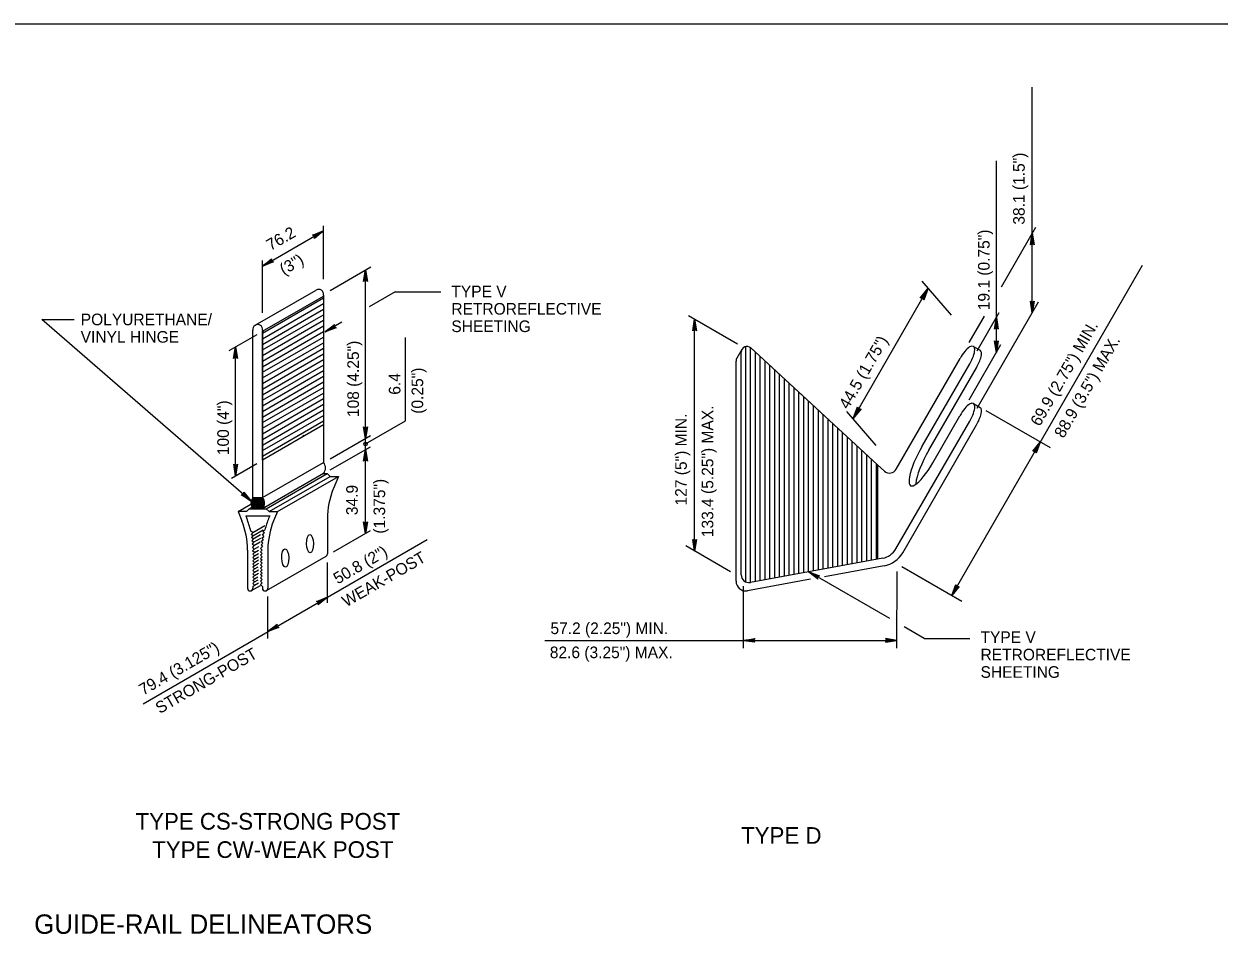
# Model space of a CAD drawing. Extents: x 640253 to 641999, y 298458 to 299646.
# Drawn here: x 640490.1 to 640798.8, y 298801.7 to 299036.6 of the extents above; entities that cross this region are included whole.
import ezdxf

# ---------------------------------------------------------------- set-up
doc = ezdxf.new("R2010")
doc.units = 0
doc.layers.add('1', color=7, linetype='Continuous')
doc.layers.add('2', color=7, linetype='Continuous')

msp = doc.modelspace()

# ---------------------------------------------------------------- linework, layer by layer
at = {"layer": '1'}
msp.add_line((640293.31, 299036.63), (641079.31, 299036.63), dxfattribs=at)
at = {"layer": '2'}
for p, q in [((640750.54, 298962.09), (640750.55, 299020.27)), ((640741.28, 298960.84), (640741.29, 299001.32)), ((640551.76, 298974.1), (640567.51, 298983.19)), ((640567.51, 298970.72), (640567.51, 298984.49)), ((640742.56, 298968.76), (640751.44, 298984.14)), ((640551.76, 298962.03), (640551.76, 298975.56)), ((640569.19, 298967.84), (640579.72, 298973.91)), ((640729.75, 298889.07), (640778.99, 298974.33)), ((640578.36, 298929.66), (640578.36, 298973.13)), ((640549.88, 298958.85), (640565.62, 298967.94)), ((640586.04, 298967.48), (640579.26, 298963.62)), ((640586.04, 298967.48), (640597.84, 298967.48)), ((640704.26, 298934.75), (640723.7, 298968.41)), ((640729.66, 298961.46), (640722.11, 298970.27)), ((640551.76, 298956.81), (640567.51, 298965.9)), ((640551.76, 298955.36), (640567.51, 298964.45)), ((640567.51, 298966.65), (640567.51, 298923.44)), ((640736.28, 298937.41), (640752.15, 298964.88)), ((640551.76, 298953.92), (640567.51, 298963.01)), ((640551.76, 298952.48), (640567.51, 298961.56)), ((640674.43, 298954.01), (640661.77, 298961.32)), ((640734.29, 298954.44), (640738.18, 298961.17)), ((640736.31, 298952.24), (640742.03, 298962.14)), ((640494.74, 298960.33), (640503.1, 298960.33)), ((640548.82, 298913.46), (640494.74, 298960.33)), ((640551.76, 298951.03), (640567.51, 298960.12)), ((640551.76, 298949.59), (640567.51, 298958.68)), ((640572.24, 298959.61), (640567.94, 298957.16)), ((640663.36, 298900.57), (640663.36, 298960.4)), ((640741.28, 298951.81), (640741.28, 298960.84)), ((640543.17, 298952.33), (640550.37, 298956.48)), ((640549.27, 298914.35), (640549.27, 298957.56)), ((640551.76, 298957.56), (640551.76, 298914.35)), ((640551.76, 298957.02), (640551.99, 298957.42)), ((640551.76, 298957.06), (640551.96, 298957.4)), ((640551.76, 298948.15), (640567.51, 298957.24)), ((640551.76, 298946.7), (640567.51, 298955.79)), ((640588.68, 298934.17), (640588.68, 298955.67)), ((640544.78, 298919.99), (640544.78, 298953.26)), ((640551.76, 298945.26), (640567.51, 298954.35)), ((640551.76, 298943.82), (640567.51, 298952.9)), ((640674.3, 298950.42), (640675.62, 298952.7)), ((640675.38, 298894.43), (640675.38, 298951.88)), ((640676.55, 298892.62), (640676.56, 298953.34)), ((640677.8, 298892.48), (640677.8, 298953.05)), ((640695.7, 298936.55), (640677.87, 298953)), ((640677.9, 298952.98), (640710.55, 298922.83)), ((640679.05, 298892.71), (640679.05, 298951.91)), ((640734.24, 298939.62), (640742.46, 298953.85)), ((640735.34, 298953.4), (640737.1, 298952.38)), ((640551.76, 298942.37), (640567.51, 298951.46)), ((640551.76, 298940.93), (640567.51, 298950.02)), ((640674.06, 298892.76), (640674.06, 298949.61)), ((640680.3, 298892.93), (640680.31, 298950.76)), ((640681.55, 298893.16), (640681.56, 298949.61)), ((640715.38, 298921.69), (640731.89, 298950.28)), ((640722.09, 298927.61), (640734.39, 298948.9)), ((640551.76, 298939.49), (640567.51, 298948.57)), ((640551.76, 298938.04), (640567.51, 298947.13)), ((640551.76, 298936.6), (640567.51, 298945.69)), ((640682.8, 298893.39), (640682.8, 298948.45)), ((640684.05, 298893.62), (640684.05, 298947.3)), ((640685.3, 298893.85), (640685.3, 298946.14)), ((640723.82, 298926.61), (640736.12, 298947.9)), ((640551.76, 298935.16), (640567.51, 298944.24)), ((640551.76, 298933.71), (640567.51, 298942.8)), ((640686.55, 298894.08), (640686.55, 298944.99)), ((640687.8, 298894.31), (640687.8, 298943.83)), ((640689.05, 298894.54), (640689.05, 298942.68)), ((640551.76, 298932.27), (640567.51, 298941.36)), ((640551.76, 298930.82), (640567.51, 298939.91)), ((640690.3, 298894.77), (640690.3, 298941.53)), ((640691.55, 298895), (640691.55, 298940.37)), ((640551.76, 298929.38), (640567.51, 298938.47)), ((640551.76, 298927.94), (640567.51, 298937.03)), ((640692.8, 298895.23), (640692.8, 298939.22)), ((640694.05, 298895.46), (640694.06, 298938.06)), ((640695.3, 298895.69), (640695.3, 298936.91)), ((640710.22, 298927.8), (640702.67, 298936.61)), ((640735.35, 298938.66), (640737.12, 298937.64)), ((640755.23, 298927.18), (640738.62, 298936.77)), ((640551.76, 298926.5), (640567.51, 298935.58)), ((640551.76, 298925.05), (640567.51, 298934.14)), ((640578.36, 298928.21), (640588.68, 298934.17)), ((640696.55, 298895.92), (640696.55, 298935.76)), ((640697.8, 298896.14), (640697.8, 298934.6)), ((640699.05, 298896.37), (640699.05, 298933.45)), ((640715.35, 298901.15), (640734.39, 298934.12)), ((640724.85, 298923.36), (640731.87, 298935.51)), ((640562.12, 298930), (640562.43, 298930.53)), ((640569.22, 298924.38), (640579.61, 298930.38)), ((640700.3, 298896.6), (640700.3, 298932.29)), ((640701.55, 298896.83), (640701.55, 298931.14)), ((640717.08, 298900.15), (640736.12, 298933.12)), ((640569.22, 298921.5), (640579.61, 298927.49)), ((640578.36, 298926.77), (640578.36, 298929.66)), ((640702.8, 298897.06), (640702.8, 298929.98)), ((640704.05, 298897.29), (640704.05, 298928.83)), ((640705.3, 298897.52), (640705.3, 298927.68)), ((640578.36, 298905.13), (640578.36, 298926.77)), ((640706.55, 298897.75), (640706.55, 298926.52)), ((640707.8, 298897.98), (640707.8, 298925.37)), ((640709.05, 298898.21), (640709.05, 298924.21)), ((640543.72, 298919.38), (640550.3, 298923.18)), ((640551.76, 298914.35), (640567.51, 298923.44)), ((640710.3, 298898.44), (640710.3, 298923.06)), ((640712.37, 298921.15), (640710.55, 298922.83)), ((640710.55, 298922.83), (640710.55, 298898.48)), ((640567.51, 298920.55), (640551.76, 298911.46)), ((640552.74, 298911.46), (640568.49, 298920.55)), ((640553.45, 298910.75), (640569.2, 298919.85)), ((640555.6, 298910.75), (640571.35, 298919.85)), ((640567.51, 298920.55), (640568.49, 298920.55)), ((640568.49, 298920.55), (640569.2, 298919.85)), ((640569.2, 298919.85), (640571.35, 298919.85)), ((640571.35, 298919.85), (640570.01, 298916.58)), ((640545.43, 298910.75), (640548.77, 298912.67)), ((640548.29, 298911.46), (640549, 298911.87)), ((640548.77, 298913.01), (640550.11, 298914.35)), ((640548.79, 298912.68), (640550.46, 298914.35)), ((640548.84, 298912.38), (640550.81, 298914.35)), ((640548.85, 298913.45), (640549.75, 298914.35)), ((640548.92, 298912.1), (640551.17, 298914.35)), ((640549.01, 298911.84), (640551.52, 298914.35)), ((640549.07, 298914.03), (640549.4, 298914.35)), ((640549.15, 298911.63), (640551.81, 298914.29)), ((640549.27, 298914.35), (640551.76, 298914.35)), ((640549.34, 298911.46), (640551.95, 298914.07)), ((640549.69, 298911.46), (640552.08, 298913.85)), ((640550.04, 298911.46), (640552.16, 298913.57)), ((640550.4, 298911.46), (640552.23, 298913.3)), ((640550.75, 298911.46), (640552.27, 298912.98)), ((640551.1, 298911.46), (640552.24, 298912.6)), ((640551.46, 298911.46), (640552.13, 298912.14)), ((640547.58, 298910.75), (640545.43, 298910.75)), ((640545.43, 298910.75), (640546.4, 298908.39)), ((640547.42, 298909.64), (640553.61, 298909.64)), ((640547.42, 298909.64), (640547.68, 298908.99)), ((640548.29, 298911.46), (640547.58, 298910.75)), ((640548.29, 298911.46), (640552.74, 298911.46)), ((640551.76, 298911.46), (640551.77, 298911.46)), ((640552.74, 298911.46), (640553.45, 298910.75)), ((640553.61, 298909.64), (640553.34, 298908.99)), ((640553.45, 298910.75), (640555.6, 298910.75)), ((640555.6, 298910.75), (640554.63, 298908.39)), ((640568.51, 298908.92), (640568.51, 298899.86)), ((640549.2, 298905.41), (640548.72, 298905.74)), ((640549.22, 298905.39), (640552.36, 298907.2)), ((640549.25, 298904.5), (640551.95, 298906.06)), ((640551.86, 298905.67), (640552.38, 298906.04)), ((640551.86, 298905.67), (640552.21, 298905.19)), ((640570.1, 298900.36), (640579.61, 298905.86)), ((640520.9, 298861.15), (640594.28, 298903.52)), ((640549.22, 298905.39), (640548.81, 298904.8)), ((640549.25, 298904.5), (640548.81, 298904.8)), ((640549.25, 298904.5), (640548.93, 298904.06)), ((640549.35, 298903.69), (640548.93, 298904.06)), ((640549.35, 298903.69), (640548.96, 298903.24)), ((640549.45, 298902.82), (640548.96, 298903.24)), ((640549.45, 298902.82), (640549.06, 298902.37)), ((640549.35, 298903.69), (640551.26, 298904.8)), ((640549.45, 298902.82), (640551.29, 298903.89)), ((640549.52, 298901.97), (640551.16, 298902.92)), ((640551.37, 298902.18), (640551.83, 298902.58)), ((640551.44, 298903.03), (640551.93, 298903.45)), ((640551.44, 298903.03), (640551.83, 298902.58)), ((640551.54, 298903.9), (640552.06, 298904.35)), ((640551.54, 298903.9), (640551.93, 298903.45)), ((640551.71, 298904.83), (640552.21, 298905.19)), ((640551.71, 298904.83), (640552.06, 298904.35)), ((640547.88, 298900.83), (640547.88, 298890.99)), ((640549.52, 298901.97), (640549.06, 298902.37)), ((640549.52, 298901.97), (640549.13, 298901.52)), ((640549.61, 298901.04), (640549.13, 298901.52)), ((640549.61, 298901.04), (640549.19, 298900.62)), ((640549.65, 298900.17), (640549.19, 298900.62)), ((640549.65, 298900.17), (640549.23, 298899.75)), ((640549.66, 298899.31), (640549.23, 298899.75)), ((640549.66, 298899.31), (640549.24, 298898.89)), ((640549.61, 298901.04), (640550.83, 298901.75)), ((640549.65, 298900.17), (640550.76, 298900.81)), ((640549.66, 298899.31), (640550.73, 298899.94)), ((640551.23, 298899.52), (640551.66, 298899.95)), ((640551.23, 298899.52), (640551.65, 298899.1)), ((640551.24, 298900.37), (640551.7, 298900.83)), ((640551.24, 298900.37), (640551.66, 298899.95)), ((640551.28, 298901.25), (640551.76, 298901.73)), ((640551.28, 298901.25), (640551.7, 298900.83)), ((640551.37, 298902.18), (640551.76, 298901.73)), ((640553.15, 298900.83), (640553.15, 298890.99)), ((640672.59, 298895.24), (640661.07, 298901.9)), ((640549.66, 298898.47), (640549.24, 298898.89)), ((640549.66, 298898.47), (640549.24, 298898.05)), ((640549.66, 298897.63), (640549.24, 298898.05)), ((640549.66, 298897.63), (640549.24, 298897.21)), ((640549.66, 298896.79), (640549.24, 298897.21)), ((640549.66, 298896.79), (640549.24, 298896.37)), ((640549.66, 298895.95), (640549.24, 298896.37)), ((640549.66, 298898.47), (640550.75, 298899.11)), ((640549.66, 298897.63), (640550.73, 298898.26)), ((640549.66, 298896.79), (640550.73, 298897.41)), ((640549.66, 298895.95), (640550.62, 298896.51)), ((640551.23, 298898.68), (640551.65, 298899.1)), ((640551.23, 298898.68), (640551.65, 298898.26)), ((640551.23, 298897.84), (640551.65, 298898.26)), ((640551.23, 298897.84), (640551.65, 298897.42)), ((640551.23, 298897), (640551.65, 298897.42)), ((640551.23, 298897), (640551.65, 298896.58)), ((640551.23, 298896.16), (640551.65, 298896.58)), ((640552.8, 298890.37), (640568.16, 298899.25)), ((640568.51, 298887.18), (640568.51, 298897.6)), ((640710.55, 298898.48), (640677.74, 298892.47)), ((640712.28, 298896.77), (640696.92, 298893.95)), ((640711.92, 298898.73), (640710.55, 298898.48)), ((640732.35, 298887.57), (640716.86, 298896.51)), ((640549.66, 298895.95), (640549.24, 298895.53)), ((640549.66, 298895.11), (640549.24, 298895.53)), ((640549.66, 298895.11), (640549.24, 298894.69)), ((640549.66, 298894.27), (640549.24, 298894.69)), ((640549.66, 298894.27), (640549.24, 298893.85)), ((640549.66, 298893.43), (640549.24, 298893.85)), ((640549.66, 298893.43), (640549.24, 298893.01)), ((640549.66, 298895.11), (640550.7, 298895.72)), ((640549.66, 298894.27), (640550.71, 298894.88)), ((640549.66, 298893.43), (640550.52, 298893.93)), ((640549.66, 298892.59), (640550.62, 298893.15)), ((640551.23, 298896.16), (640551.65, 298895.74)), ((640551.23, 298895.32), (640551.65, 298895.74)), ((640551.23, 298895.32), (640551.65, 298894.9)), ((640551.23, 298894.48), (640551.65, 298894.9)), ((640551.23, 298894.48), (640551.65, 298894.06)), ((640551.23, 298893.64), (640551.65, 298894.06)), ((640551.23, 298893.64), (640551.65, 298893.22)), ((640551.23, 298892.8), (640551.65, 298893.22)), ((640693.24, 298893.28), (640677.02, 298890.3)), ((640713.78, 298883.12), (640692.81, 298895.23)), ((640715.61, 298875.5), (640715.62, 298895.26)), ((640548.95, 298890.37), (640551.25, 298891.7)), ((640549.66, 298892.59), (640549.24, 298893.01)), ((640549.66, 298892.59), (640549.24, 298892.17)), ((640549.66, 298891.75), (640549.24, 298892.17)), ((640549.3, 298891.4), (640549.66, 298891.75)), ((640549.3, 298891.4), (640549.3, 298890.99)), ((640549.66, 298891.75), (640550.71, 298892.36)), ((640551.23, 298892.8), (640551.65, 298892.38)), ((640551.23, 298891.96), (640551.65, 298892.38)), ((640551.23, 298891.96), (640551.73, 298891.46)), ((640551.73, 298891.46), (640551.73, 298890.99)), ((640675.94, 298875.5), (640675.94, 298891.49)), ((640553.15, 298878.02), (640553.15, 298888.85)), ((640722.62, 298878.01), (640717.48, 298880.98)), ((640722.62, 298878.01), (640734.42, 298878.01)), ((640624.71, 298877.52), (640715.61, 298877.52))]:
    msp.add_line(p, q, dxfattribs=at)
for points in [[(640564.86, 298982.07), (640565.05, 298981.95), (640567.51, 298983.19), (640564.86, 298982.07), (640564.67, 298982.11), (640567.51, 298983.19), (640565.2, 298981.7), (640565.21, 298981.47), (640567.51, 298983.19), (640565.15, 298981.28), (640565.21, 298981.47)], [(640750.18, 298979.73), (640750.39, 298979.84), (640750.54, 298982.58), (640750.18, 298979.73), (640750.06, 298979.58), (640750.54, 298982.58), (640750.68, 298979.84), (640750.88, 298979.74), (640750.54, 298982.58), (640751.02, 298979.58), (640750.88, 298979.74)], [(640554.41, 298975.22), (640554.22, 298975.34), (640551.76, 298974.1), (640554.41, 298975.22), (640554.6, 298975.18), (640551.76, 298974.1), (640554.07, 298975.59), (640554.06, 298975.82), (640551.76, 298974.1), (640554.12, 298976.01), (640554.06, 298975.82)], [(640578, 298970.28), (640578.21, 298970.38), (640578.36, 298973.13), (640578, 298970.28), (640577.87, 298970.13), (640578.36, 298973.13), (640578.49, 298970.39), (640578.7, 298970.29), (640578.36, 298973.13), (640578.83, 298970.13), (640578.7, 298970.29)], [(640721.82, 298965.93), (640722.07, 298965.92), (640723.7, 298968.41), (640721.82, 298965.93), (640721.63, 298965.86), (640723.7, 298968.41), (640722.34, 298965.77), (640722.48, 298965.56), (640723.7, 298968.41), (640722.53, 298965.34), (640722.48, 298965.56)], [(640750.9, 298964.94), (640750.69, 298964.84), (640750.54, 298962.09), (640750.9, 298964.94), (640751.02, 298965.09), (640750.54, 298962.09), (640750.4, 298964.84), (640750.2, 298964.94), (640750.54, 298962.09), (640750.06, 298965.09), (640750.2, 298964.94)], [(640570.6, 298958.26), (640570.4, 298958.39), (640567.94, 298957.16), (640570.6, 298958.26), (640570.79, 298958.22), (640567.94, 298957.16), (640570.26, 298958.64), (640570.25, 298958.86), (640567.94, 298957.16), (640570.31, 298959.06), (640570.25, 298958.86)], [(640663, 298957.55), (640663.21, 298957.66), (640663.36, 298960.4), (640663, 298957.55), (640662.88, 298957.4), (640663.36, 298960.4), (640663.49, 298957.66), (640663.7, 298957.56), (640663.36, 298960.4), (640663.83, 298957.4), (640663.7, 298957.56)], [(640740.92, 298957.99), (640741.13, 298958.1), (640741.28, 298960.84), (640740.92, 298957.99), (640740.8, 298957.84), (640741.28, 298960.84), (640741.42, 298958.1), (640741.62, 298958), (640741.28, 298960.84), (640741.76, 298957.84), (640741.62, 298958)], [(640544.43, 298950.41), (640544.63, 298950.51), (640544.78, 298953.26), (640544.43, 298950.41), (640544.3, 298950.26), (640544.78, 298953.26), (640544.92, 298950.51), (640545.12, 298950.41), (640544.78, 298953.26), (640545.26, 298950.26), (640545.12, 298950.41)], [(640741.64, 298954.66), (640741.43, 298954.55), (640741.28, 298951.81), (640741.64, 298954.66), (640741.76, 298954.81), (640741.28, 298951.81), (640741.15, 298954.55), (640740.94, 298954.65), (640741.28, 298951.81), (640740.81, 298954.81), (640740.94, 298954.65)], [(640706.14, 298937.23), (640705.89, 298937.24), (640704.26, 298934.75), (640706.14, 298937.23), (640706.34, 298937.3), (640704.26, 298934.75), (640705.62, 298937.39), (640705.48, 298937.6), (640704.26, 298934.75), (640705.44, 298937.82), (640705.48, 298937.6)], [(640706.14, 298937.23), (640705.89, 298937.24), (640704.26, 298934.75), (640706.14, 298937.23), (640706.34, 298937.3), (640704.26, 298934.75), (640705.62, 298937.39), (640705.48, 298937.6), (640704.26, 298934.75), (640705.44, 298937.82), (640705.48, 298937.6)], [(640578.72, 298932.51), (640578.51, 298932.41), (640578.36, 298929.66), (640578.72, 298932.51), (640578.84, 298932.66), (640578.36, 298929.66), (640578.22, 298932.4), (640578.02, 298932.5), (640578.36, 298929.66), (640577.88, 298932.66), (640578.02, 298932.5)], [(640750.89, 298926.39), (640751.12, 298926.38), (640752.63, 298928.68), (640750.89, 298926.39), (640750.71, 298926.33), (640752.63, 298928.68), (640751.37, 298926.24), (640751.5, 298926.05), (640752.63, 298928.68), (640751.54, 298925.85), (640751.5, 298926.05)], [(640578, 298923.91), (640578.21, 298924.02), (640578.36, 298926.77), (640578, 298923.91), (640577.87, 298923.77), (640578.36, 298926.77), (640578.49, 298924.02), (640578.7, 298923.92), (640578.36, 298926.77), (640578.83, 298923.77), (640578.7, 298923.92)], [(640545.14, 298922.85), (640544.94, 298922.74), (640544.78, 298919.99), (640545.14, 298922.85), (640545.27, 298922.99), (640544.78, 298919.99), (640544.65, 298922.74), (640544.45, 298922.84), (640544.78, 298919.99), (640544.31, 298922.99), (640544.45, 298922.84)], [(640546.93, 298915.62), (640546.87, 298915.39), (640548.82, 298913.46), (640546.93, 298915.62), (640546.9, 298915.81), (640548.82, 298913.46), (640546.68, 298915.18), (640546.47, 298915.09), (640548.82, 298913.46), (640546.26, 298915.09), (640546.47, 298915.09)], [(640578.72, 298907.99), (640578.51, 298907.88), (640578.36, 298905.13), (640578.72, 298907.99), (640578.84, 298908.13), (640578.36, 298905.13), (640578.22, 298907.88), (640578.02, 298907.98), (640578.36, 298905.13), (640577.88, 298908.13), (640578.02, 298907.98)], [(640663.72, 298903.43), (640663.51, 298903.32), (640663.36, 298900.57), (640663.72, 298903.43), (640663.84, 298903.57), (640663.36, 298900.57), (640663.22, 298903.32), (640663.02, 298903.42), (640663.36, 298900.57), (640662.88, 298903.57), (640663.02, 298903.42)], [(640695.1, 298893.49), (640695.11, 298893.72), (640692.81, 298895.23), (640695.1, 298893.49), (640695.16, 298893.31), (640692.81, 298895.23), (640695.25, 298893.97), (640695.44, 298894.1), (640692.81, 298895.23), (640695.64, 298894.14), (640695.44, 298894.1)], [(640731.49, 298891.36), (640731.26, 298891.37), (640729.75, 298889.07), (640731.49, 298891.36), (640731.67, 298891.43), (640729.75, 298889.07), (640731.01, 298891.52), (640730.88, 298891.7), (640729.75, 298889.07), (640730.84, 298891.91), (640730.88, 298891.7)], [(640565.86, 298887.52), (640566.06, 298887.4), (640568.51, 298888.64), (640565.86, 298887.52), (640565.67, 298887.56), (640568.51, 298888.64), (640566.2, 298887.15), (640566.22, 298886.92), (640568.51, 298888.64), (640566.15, 298886.73), (640566.22, 298886.92)], [(640555.8, 298880.89), (640555.6, 298881.01), (640553.15, 298879.77), (640555.8, 298880.89), (640555.99, 298880.85), (640553.15, 298879.77), (640555.46, 298881.26), (640555.44, 298881.49), (640553.15, 298879.77), (640555.51, 298881.68), (640555.44, 298881.49)], [(640678.79, 298877.16), (640678.68, 298877.37), (640675.94, 298877.52), (640678.79, 298877.16), (640678.94, 298877.04), (640675.94, 298877.52), (640678.68, 298877.65), (640678.78, 298877.86), (640675.94, 298877.52), (640678.94, 298878), (640678.78, 298877.86)], [(640712.76, 298877.16), (640712.87, 298877.37), (640715.61, 298877.52), (640712.76, 298877.16), (640712.61, 298877.04), (640715.61, 298877.52), (640712.87, 298877.65), (640712.77, 298877.86), (640715.61, 298877.52), (640712.61, 298878), (640712.77, 298877.86)]]:
    msp.add_lwpolyline(points, dxfattribs=at)
msp.add_lwpolyline([(640551.76, 298924.02), (640551.76, 298957.29), (640567.51, 298966.38), (640567.51, 298933.11)], close=True, dxfattribs=at)
msp.add_circle((640578.36, 298928.21), 0.444, dxfattribs=at)
for centre, radius, start, end in [((640566.26, 298966.85), 1.26, 350.9133, 119.9792), ((640550.51, 298957.76), 1.26, 350.9133, 189.0867), ((640676.88, 298951.88), 1.5, 47.2827, 180.0033), ((640675.56, 298949.61), 1.5, 147.1819, 180.0033), ((640565.73, 298922), 2.29, 320.9923, 39.0623), ((640713.65, 298922.69), 2, 230.2615, 329.996), ((640588.76, 298908.93), 20.25, 157.7877, 180), ((640551.05, 298912.9), 2.29, 140.9377, 219.0623), ((640549.98, 298912.9), 2.29, 320.9923, 39.0623), ((640527.55, 298900.76), 21.75, 13.2354, 22.2267), ((640573.48, 298900.77), 21.75, 157.7963, 165.9872), ((640527.88, 298900.83), 20, 0, 22.2204), ((640573.15, 298900.83), 20, 157.7833, 180), ((640567.8, 298899.86), 0.709, 300.0103, 0), ((640711.02, 298903.65), 5, 280.3803, 329.996), ((640711.02, 298903.65), 7, 280.3899, 329.996), ((640677.38, 298894.43), 2, 180.0098, 280.3902), ((640548.59, 298890.99), 0.709, 180, 0), ((640552.44, 298890.99), 0.709, 180.005, 0), ((640676.56, 298892.76), 2.5, 179.9993, 280.3971)]:
    msp.add_arc(centre, radius, start, end, dxfattribs=at)
for centre, major_axis, ratio, start_param, end_param in [((640733.31, 298949.88), (2.03, 3.52), 0.351581, 4.636261, 7.943286), ((640735.04, 298948.88), (2.03, 3.52), 0.351581, 4.636261, 6.257684), ((640733.3, 298935.11), (2.05, 3.55), 0.351581, 4.636261, 7.943286), ((640735.03, 298934.11), (2.05, 3.55), 0.351581, 4.636261, 6.250381), ((640723.43, 298925.41), (4.28, 7.98), 0.247592, 1.425353, 4.587399), ((640725.16, 298924.41), (4.28, 7.98), 0.247592, 1.425353, 2.620687)]:
    msp.add_ellipse(centre, major_axis=major_axis, ratio=ratio, start_param=start_param, end_param=end_param, dxfattribs=at)
for centre in [(640564.02, 298902.48), (640557.63, 298898.79)]:
    msp.add_ellipse(centre, major_axis=(0.05, -2.36), ratio=0.379302, dxfattribs=at)

# ---------------------------------------------------------------- texts
for s, rotation, p in [('38.1 (1.5") ', 89.996, (640748.6, 298984.81)), ('76.2', 30, (640553.85, 298977.98)), ('19.1 (0.75") ', 89.996, (640739.54, 298962.72)), ('(3")', 30, (640557.26, 298971.71)), ('69.9 (2.75") MIN.', 59.996, (640752.47, 298932.55)), ('44.5 (1.75") ', 59.996, (640703.01, 298936.97)), ('88.9 (3.5") MAX.', 59.996, (640758.63, 298929.51)), ('108 (4.25")', 90, (640576.66, 298935.15)), ('6.4 ', 90, (640587.37, 298940.92)), ('(0.25")', 90, (640593.25, 298936.01)), ('100 (4")', 90, (640543.08, 298925.32)), ('133.4 (5.25") MAX.', 89.996, (640668.18, 298904.15)), ('127 (5") MIN.', 89.996, (640661.33, 298912.33)), ('(1.375")', 90, (640583.43, 298905.07)), ('34.9', 90, (640576.36, 298909.83)), ('50.8 (2")', 30, (640571.17, 298891.92)), ('WEAK-POST', 30, (640573.38, 298886)), ('79.4 (3.125")', 30, (640520.96, 298863.22)), ('STRONG-POST', 30, (640525.22, 298858.48))]:
    msp.add_text(s, height=3, rotation=rotation, dxfattribs=at).set_placement(p)
for s, height, p in [('TYPE V', 3, (640600.53, 298966.09)), ('RETROREFLECTIVE', 3, (640600.53, 298961.59)), ('POLYURETHANE/', 3, (640504.82, 298958.85)), ('SHEETING', 3, (640600.53, 298957.09)), ('VINYL HINGE  ', 3, (640504.8, 298954.35)), ('57.2 (2.25") MIN.', 3, (640626.12, 298879.14)), ('TYPE V', 3, (640737.19, 298876.85)), ('82.6 (3.25") MAX.', 3, (640625.95, 298872.92)), ('RETROREFLECTIVE', 3, (640737.19, 298872.35)), ('SHEETING', 3, (640737.19, 298867.85)), ('TYPE CS-STRONG POST', 4.3, (640518.97, 298828.66)), ('TYPE D', 4.3, (640675.35, 298825.01)), ('TYPE CW-WEAK POST', 4.3, (640523.27, 298821.36)), ('GUIDE-RAIL DELINEATORS', 5, (640492.79, 298801.78))]:
    msp.add_text(s, height=height, dxfattribs=at).set_placement(p)

doc.saveas('drawing.dxf')
